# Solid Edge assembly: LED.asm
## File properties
Author: f_grande
Template: Normal.asm
Last saved by: f_grande
Revision: 7
Application: Solid Edge
Tipo di contenuto documento: 1
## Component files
base.par
cover.par
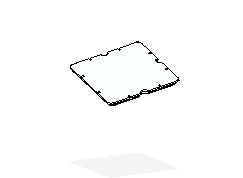
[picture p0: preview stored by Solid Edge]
